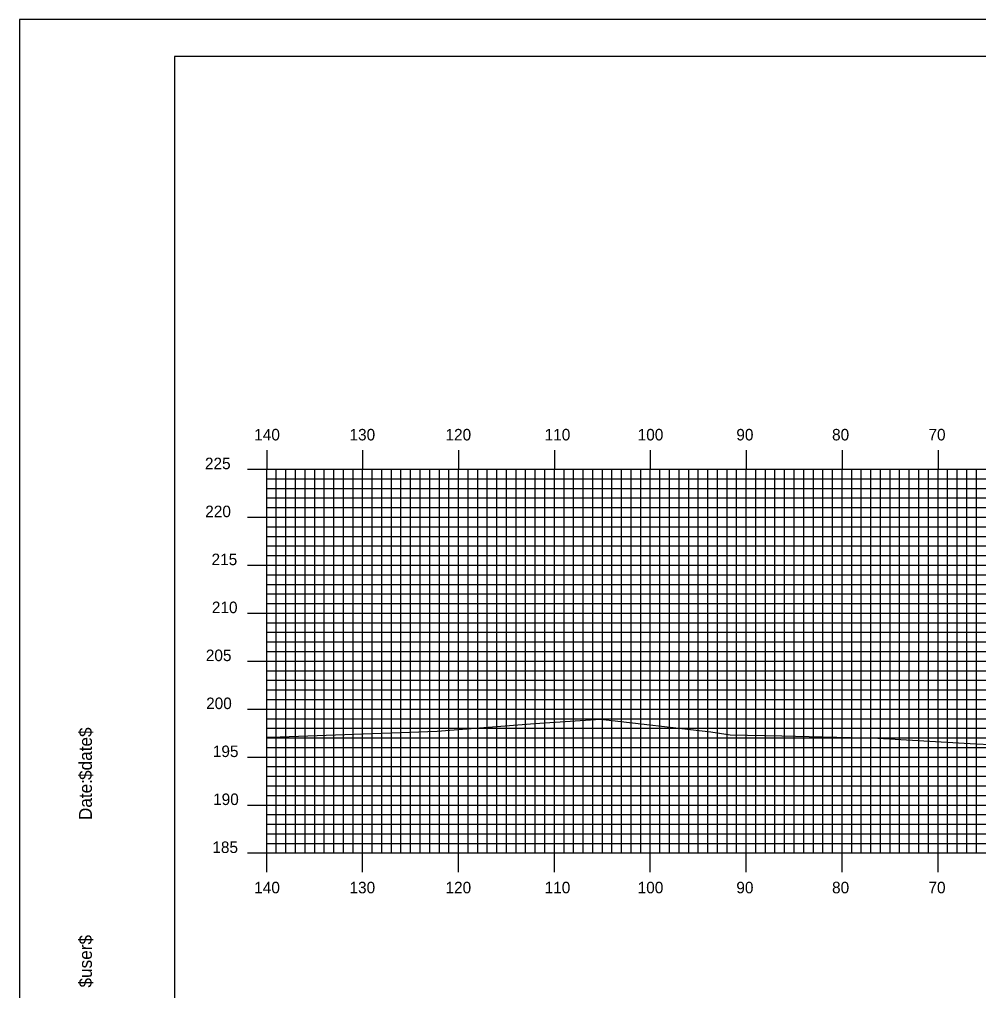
# Model space of a CAD drawing. Extents: x 1812161 to 1812504, y 442591 to 442811.
# Drawn here: x 1812160.6 to 1812260.7, y 442709.3 to 442810.5 of the extents above; entities that cross this region are included whole.
import ezdxf

# ---------------------------------------------------------------- set-up
doc = ezdxf.new("R2010")
doc.units = 0
for name, color, linetype in [('BORDER', 7, 'Continuous'), ('H_V ANNOTATION', 7, 'Continuous'), ('MAJOR', 7, 'Continuous'), ('MINOR', 7, 'Continuous'), ('PLOT BOUNDARY', 7, 'Continuous'), ('S_Roadway_Centerline', 7, 'Continuous')]:
    doc.layers.add(name, color=color, linetype=linetype)

msp = doc.modelspace()

# ---------------------------------------------------------------- linework, layer by layer
at = {"layer": 'BORDER'}
msp.add_lwpolyline([(1812176.83, 442596.67), (1812496.83, 442596.67), (1812496.83, 442806.67), (1812176.83, 442806.67)], close=True, dxfattribs=at)
at = {"layer": 'MAJOR'}
for p, q in [((1812186.43, 442765.67), (1812186.43, 442763.67)), ((1812196.43, 442765.67), (1812196.43, 442763.67)), ((1812206.43, 442765.67), (1812206.43, 442763.67)), ((1812216.43, 442765.67), (1812216.43, 442763.67)), ((1812226.43, 442765.67), (1812226.43, 442763.67)), ((1812236.43, 442765.67), (1812236.43, 442763.67)), ((1812246.43, 442765.67), (1812246.43, 442763.67)), ((1812256.43, 442765.67), (1812256.43, 442763.67)), ((1812184.42, 442763.67), (1812186.43, 442763.67)), ((1812186.43, 442763.67), (1812466.43, 442763.67)), ((1812186.43, 442723.67), (1812186.43, 442763.67)), ((1812186.43, 442723.67), (1812186.43, 442763.67)), ((1812186.43, 442763.67), (1812466.43, 442763.67)), ((1812196.43, 442723.67), (1812196.43, 442763.67)), ((1812206.43, 442723.67), (1812206.43, 442763.67)), ((1812216.43, 442723.67), (1812216.43, 442763.67)), ((1812226.43, 442723.67), (1812226.43, 442763.67)), ((1812236.43, 442723.67), (1812236.43, 442763.67)), ((1812246.43, 442723.67), (1812246.43, 442763.67)), ((1812256.43, 442723.67), (1812256.43, 442763.67)), ((1812184.42, 442758.67), (1812186.43, 442758.67)), ((1812186.43, 442758.67), (1812466.43, 442758.67)), ((1812184.42, 442753.67), (1812186.43, 442753.67)), ((1812186.43, 442753.67), (1812466.43, 442753.67)), ((1812184.42, 442748.67), (1812186.43, 442748.67)), ((1812186.43, 442748.67), (1812466.43, 442748.67)), ((1812184.42, 442743.67), (1812186.43, 442743.67)), ((1812186.43, 442743.67), (1812466.43, 442743.67)), ((1812184.42, 442738.67), (1812186.43, 442738.67)), ((1812186.43, 442738.67), (1812466.43, 442738.67)), ((1812184.42, 442733.67), (1812186.43, 442733.67)), ((1812186.43, 442733.67), (1812466.43, 442733.67)), ((1812184.42, 442728.67), (1812186.43, 442728.67)), ((1812186.43, 442728.67), (1812466.43, 442728.67)), ((1812184.42, 442723.67), (1812186.43, 442723.67)), ((1812186.43, 442723.67), (1812466.43, 442723.67)), ((1812186.43, 442723.67), (1812466.43, 442723.67)), ((1812186.43, 442721.66), (1812186.43, 442723.67)), ((1812196.43, 442721.66), (1812196.43, 442723.67)), ((1812206.43, 442721.66), (1812206.43, 442723.67)), ((1812216.43, 442721.66), (1812216.43, 442723.67)), ((1812226.43, 442721.66), (1812226.43, 442723.67)), ((1812236.43, 442721.66), (1812236.43, 442723.67)), ((1812246.43, 442721.66), (1812246.43, 442723.67)), ((1812256.43, 442721.66), (1812256.43, 442723.67))]:
    msp.add_line(p, q, dxfattribs=at)
at = {"layer": 'MINOR'}
for p, q in [((1812187.43, 442723.67), (1812187.43, 442763.67)), ((1812188.43, 442723.67), (1812188.43, 442763.67)), ((1812189.43, 442723.67), (1812189.43, 442763.67)), ((1812190.43, 442723.67), (1812190.43, 442763.67)), ((1812191.43, 442723.67), (1812191.43, 442763.67)), ((1812192.43, 442723.67), (1812192.43, 442763.67)), ((1812193.43, 442723.67), (1812193.43, 442763.67)), ((1812194.43, 442723.67), (1812194.43, 442763.67)), ((1812195.43, 442723.67), (1812195.43, 442763.67)), ((1812197.43, 442723.67), (1812197.43, 442763.67)), ((1812198.43, 442723.67), (1812198.43, 442763.67)), ((1812199.43, 442723.67), (1812199.43, 442763.67)), ((1812200.43, 442723.67), (1812200.43, 442763.67)), ((1812201.43, 442723.67), (1812201.43, 442763.67)), ((1812202.43, 442723.67), (1812202.43, 442763.67)), ((1812203.43, 442723.67), (1812203.43, 442763.67)), ((1812204.43, 442723.67), (1812204.43, 442763.67)), ((1812205.43, 442723.67), (1812205.43, 442763.67)), ((1812207.43, 442723.67), (1812207.43, 442763.67)), ((1812208.43, 442723.67), (1812208.43, 442763.67)), ((1812209.43, 442723.67), (1812209.43, 442763.67)), ((1812210.43, 442723.67), (1812210.43, 442763.67)), ((1812211.43, 442723.67), (1812211.43, 442763.67)), ((1812212.43, 442723.67), (1812212.43, 442763.67)), ((1812213.43, 442723.67), (1812213.43, 442763.67)), ((1812214.43, 442723.67), (1812214.43, 442763.67)), ((1812215.43, 442723.67), (1812215.43, 442763.67)), ((1812217.43, 442723.67), (1812217.43, 442763.67)), ((1812218.43, 442723.67), (1812218.43, 442763.67)), ((1812219.43, 442723.67), (1812219.43, 442763.67)), ((1812220.43, 442723.67), (1812220.43, 442763.67)), ((1812221.43, 442723.67), (1812221.43, 442763.67)), ((1812222.43, 442723.67), (1812222.43, 442763.67)), ((1812223.43, 442723.67), (1812223.43, 442763.67)), ((1812224.43, 442723.67), (1812224.43, 442763.67)), ((1812225.43, 442723.67), (1812225.43, 442763.67)), ((1812227.43, 442723.67), (1812227.43, 442763.67)), ((1812228.43, 442723.67), (1812228.43, 442763.67)), ((1812229.43, 442723.67), (1812229.43, 442763.67)), ((1812230.43, 442723.67), (1812230.43, 442763.67)), ((1812231.43, 442723.67), (1812231.43, 442763.67)), ((1812232.43, 442723.67), (1812232.43, 442763.67)), ((1812233.43, 442723.67), (1812233.43, 442763.67)), ((1812234.43, 442723.67), (1812234.43, 442763.67)), ((1812235.43, 442723.67), (1812235.43, 442763.67)), ((1812237.43, 442723.67), (1812237.43, 442763.67)), ((1812238.43, 442723.67), (1812238.43, 442763.67)), ((1812239.43, 442723.67), (1812239.43, 442763.67)), ((1812240.43, 442723.67), (1812240.43, 442763.67)), ((1812241.43, 442723.67), (1812241.43, 442763.67)), ((1812242.43, 442723.67), (1812242.43, 442763.67)), ((1812243.43, 442723.67), (1812243.43, 442763.67)), ((1812244.43, 442723.67), (1812244.43, 442763.67)), ((1812245.43, 442723.67), (1812245.43, 442763.67)), ((1812247.43, 442723.67), (1812247.43, 442763.67)), ((1812248.43, 442723.67), (1812248.43, 442763.67)), ((1812249.43, 442723.67), (1812249.43, 442763.67)), ((1812250.43, 442723.67), (1812250.43, 442763.67)), ((1812251.43, 442723.67), (1812251.43, 442763.67)), ((1812252.43, 442723.67), (1812252.43, 442763.67)), ((1812253.43, 442723.67), (1812253.43, 442763.67)), ((1812254.43, 442723.67), (1812254.43, 442763.67)), ((1812255.43, 442723.67), (1812255.43, 442763.67)), ((1812257.43, 442723.67), (1812257.43, 442763.67)), ((1812258.43, 442723.67), (1812258.43, 442763.67)), ((1812259.43, 442723.67), (1812259.43, 442763.67)), ((1812260.43, 442723.67), (1812260.43, 442763.67)), ((1812186.43, 442762.67), (1812466.43, 442762.67)), ((1812186.43, 442762.67), (1812188.43, 442762.67)), ((1812186.43, 442761.67), (1812466.43, 442761.67)), ((1812186.43, 442761.67), (1812188.43, 442761.67)), ((1812186.43, 442760.67), (1812466.43, 442760.67)), ((1812186.43, 442760.67), (1812188.43, 442760.67)), ((1812186.43, 442759.67), (1812466.43, 442759.67)), ((1812186.43, 442759.67), (1812188.43, 442759.67)), ((1812186.43, 442757.67), (1812466.43, 442757.67)), ((1812186.43, 442757.67), (1812188.43, 442757.67)), ((1812186.43, 442756.67), (1812466.43, 442756.67)), ((1812186.43, 442756.67), (1812188.43, 442756.67)), ((1812186.43, 442755.67), (1812466.43, 442755.67)), ((1812186.43, 442755.67), (1812188.43, 442755.67)), ((1812186.43, 442754.67), (1812466.43, 442754.67)), ((1812186.43, 442754.67), (1812188.43, 442754.67)), ((1812186.43, 442752.67), (1812466.43, 442752.67)), ((1812186.43, 442752.67), (1812188.43, 442752.67)), ((1812186.43, 442751.67), (1812466.43, 442751.67)), ((1812186.43, 442751.67), (1812188.43, 442751.67)), ((1812186.43, 442750.67), (1812466.43, 442750.67)), ((1812186.43, 442750.67), (1812188.43, 442750.67)), ((1812186.43, 442749.67), (1812466.43, 442749.67)), ((1812186.43, 442749.67), (1812188.43, 442749.67)), ((1812186.43, 442747.67), (1812466.43, 442747.67)), ((1812186.43, 442747.67), (1812188.43, 442747.67)), ((1812186.43, 442746.67), (1812466.43, 442746.67)), ((1812186.43, 442746.67), (1812188.43, 442746.67)), ((1812186.43, 442745.67), (1812466.43, 442745.67)), ((1812186.43, 442745.67), (1812188.43, 442745.67)), ((1812186.43, 442744.67), (1812466.43, 442744.67)), ((1812186.43, 442744.67), (1812188.43, 442744.67)), ((1812186.43, 442742.67), (1812466.43, 442742.67)), ((1812186.43, 442742.67), (1812188.43, 442742.67)), ((1812186.43, 442741.67), (1812466.43, 442741.67)), ((1812186.43, 442741.67), (1812188.43, 442741.67)), ((1812186.43, 442740.67), (1812466.43, 442740.67)), ((1812186.43, 442740.67), (1812188.43, 442740.67)), ((1812186.43, 442739.67), (1812466.43, 442739.67)), ((1812186.43, 442739.67), (1812188.43, 442739.67)), ((1812186.43, 442737.67), (1812466.43, 442737.67)), ((1812186.43, 442737.67), (1812188.43, 442737.67)), ((1812186.43, 442736.67), (1812466.43, 442736.67)), ((1812186.43, 442736.67), (1812188.43, 442736.67)), ((1812186.43, 442735.67), (1812466.43, 442735.67)), ((1812186.43, 442735.67), (1812188.43, 442735.67)), ((1812186.43, 442734.67), (1812466.43, 442734.67)), ((1812186.43, 442734.67), (1812188.43, 442734.67)), ((1812186.43, 442732.67), (1812466.43, 442732.67)), ((1812186.43, 442732.67), (1812188.43, 442732.67)), ((1812186.43, 442731.67), (1812466.43, 442731.67)), ((1812186.43, 442731.67), (1812188.43, 442731.67)), ((1812186.43, 442730.67), (1812466.43, 442730.67)), ((1812186.43, 442730.67), (1812188.43, 442730.67)), ((1812186.43, 442729.67), (1812466.43, 442729.67)), ((1812186.43, 442729.67), (1812188.43, 442729.67)), ((1812186.43, 442727.67), (1812466.43, 442727.67)), ((1812186.43, 442727.67), (1812188.43, 442727.67)), ((1812186.43, 442726.67), (1812466.43, 442726.67)), ((1812186.43, 442726.67), (1812188.43, 442726.67)), ((1812186.43, 442725.67), (1812466.43, 442725.67)), ((1812186.43, 442725.67), (1812188.43, 442725.67)), ((1812186.43, 442724.67), (1812466.43, 442724.67)), ((1812186.43, 442724.67), (1812188.43, 442724.67))]:
    msp.add_line(p, q, dxfattribs=at)
at = {"layer": 'PLOT BOUNDARY'}
msp.add_lwpolyline([(1812160.64, 442590.55), (1812500.64, 442590.55), (1812500.64, 442810.55), (1812160.64, 442810.55)], close=True, dxfattribs=at)
at = {"layer": 'S_Roadway_Centerline'}
msp.add_lwpolyline([(1812186.43, 442735.75), (1812186.87, 442735.74), (1812204.2, 442736.37), (1812214.38, 442737.15), (1812221.25, 442737.62), (1812232.73, 442736.3), (1812234.76, 442736), (1812240.14, 442735.89), (1812250.16, 442735.65), (1812260.38, 442735.04), (1812268.2, 442734.7)], dxfattribs=at)

# ---------------------------------------------------------------- texts
at = {"layer": 'BORDER'}
for s, p in [('$date$', (1812168.2, 442731.28)), ('Date:', (1812168.2, 442727.1)), ('$user$', (1812168.2, 442709.65))]:
    msp.add_text(s, height=1.339, rotation=90, dxfattribs=at).set_placement(p)
at = {"layer": 'H_V ANNOTATION'}
for s, p in [('140', (1812185.13, 442766.67)), ('130', (1812195.06, 442766.67)), ('120', (1812205.07, 442766.67)), ('110', (1812215.41, 442766.67)), ('100', (1812225.11, 442766.67)), ('90', (1812235.4, 442766.67)), ('80', (1812245.38, 442766.67)), ('70', (1812255.43, 442766.67)), ('225', (1812179.99, 442763.67)), ('220', (1812180.02, 442758.67)), ('215', (1812180.68, 442753.67)), ('210', (1812180.71, 442748.67)), ('205', (1812180.08, 442743.67)), ('200', (1812180.11, 442738.67)), ('195', (1812180.81, 442733.67)), ('190', (1812180.84, 442728.67)), ('185', (1812180.76, 442723.67)), ('140', (1812185.13, 442719.47)), ('130', (1812195.06, 442719.47)), ('120', (1812205.07, 442719.47)), ('110', (1812215.41, 442719.47)), ('100', (1812225.11, 442719.47)), ('90', (1812235.4, 442719.47)), ('80', (1812245.38, 442719.47)), ('70', (1812255.43, 442719.47))]:
    msp.add_text(s, height=1.2, dxfattribs=at).set_placement(p)
at = {"layer": 'MAJOR'}
msp.add_text('-', height=0.012, dxfattribs=at).set_placement((1812186.42, 442723.67))

doc.saveas('drawing.dxf')
